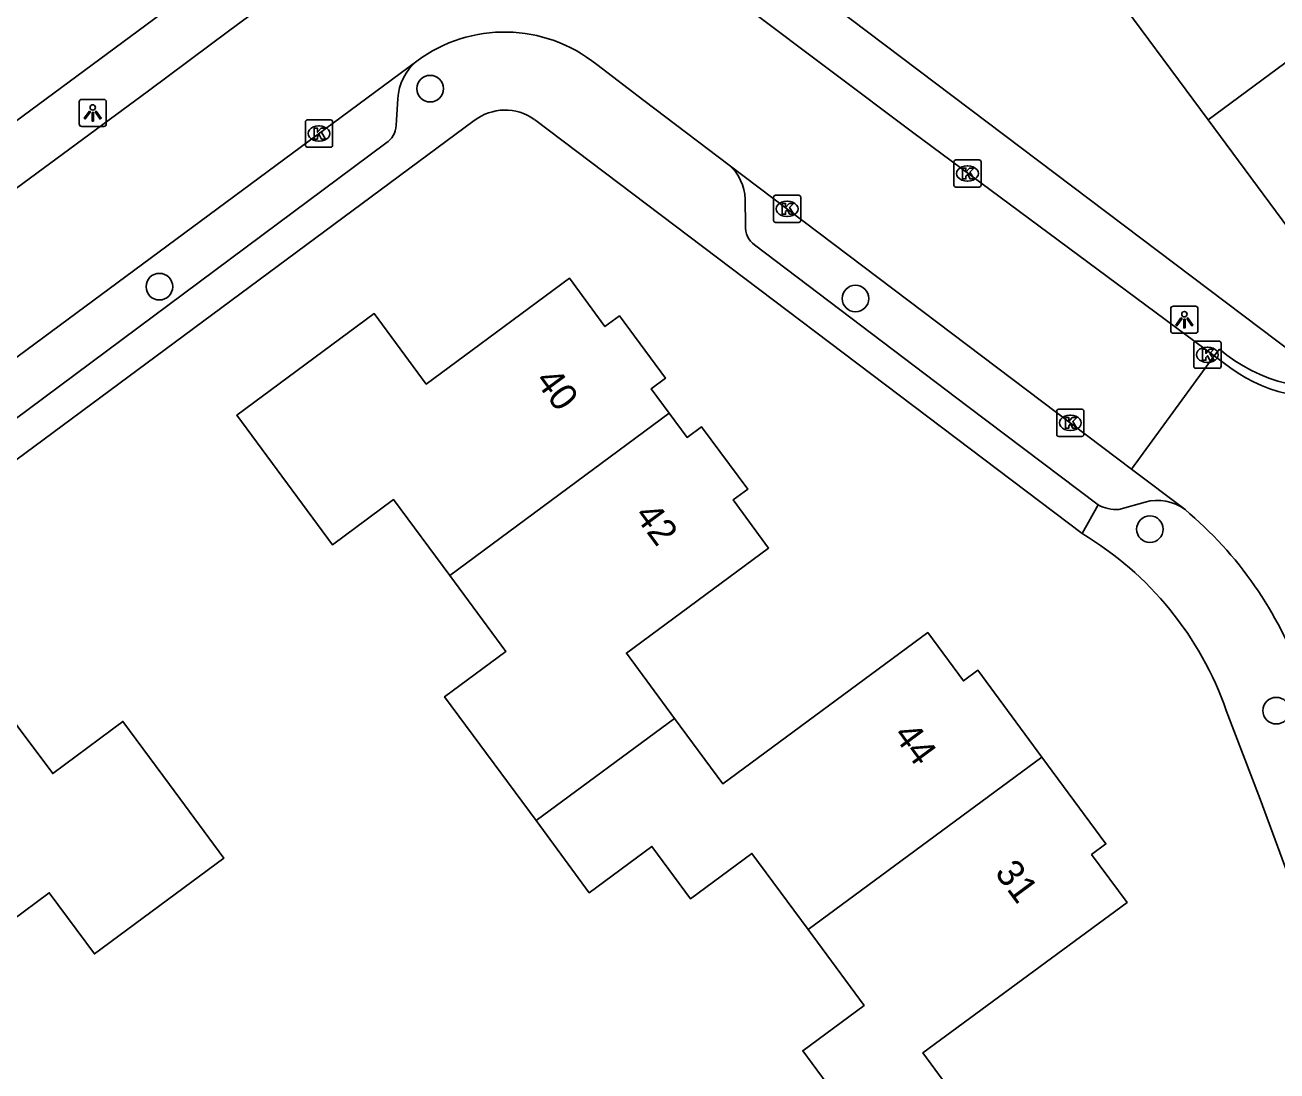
# Model space of a CAD drawing. Extents: x 163427 to 164190, y 380331 to 381641.
# Drawn here: x 163858.59 to 163904.63, y 381170.43 to 381208.88 of the extents above; entities that cross this region are included whole.
import ezdxf

# ---------------------------------------------------------------- set-up
doc = ezdxf.new("R2010")
doc.units = 0
for name, color, linetype in [('IMGEO_Boom', 7, 'Continuous'), ('IMGEO_Kolk', 7, 'Continuous'), ('IMGEO_Lichtpunt', 7, 'Continuous'), ('IMGEO_Pand', 7, 'Continuous'), ('IMGEO_Pand_nummerreeks', 7, 'Continuous'), ('IMGEO_Rijbaan_lokaal_open', 7, 'Continuous'), ('IMGEO_Voetpad_open', 7, 'Continuous')]:
    doc.layers.add(name, color=color, linetype=linetype)

msp = doc.modelspace()

# ---------------------------------------------------------------- linework, layer by layer
at = {"layer": 'IMGEO_Boom'}
for centre in [(163873.488, 381206.544), (163863.531, 381199.264), (163889.127, 381198.828), (163899.956, 381190.346), (163904.601, 381183.677)]:
    msp.add_circle(centre, 0.489, dxfattribs=at)
at = {"layer": 'IMGEO_Kolk'}
for p, q in [((163868.9, 381204.467), (163868.9, 381205.319)), ((163868.975, 381205.393), (163869.827, 381205.393)), ((163869.388, 381205.173), (163869.413, 381205.173)), ((163869.901, 381205.319), (163869.901, 381204.467)), ((163869.411, 381204.613), (163869.386, 381204.613)), ((163869.827, 381204.393), (163868.975, 381204.393)), ((163892.747, 381203), (163892.747, 381203.852)), ((163892.822, 381203.926), (163893.674, 381203.926)), ((163893.235, 381203.706), (163893.26, 381203.706)), ((163893.748, 381203.852), (163893.748, 381203)), ((163893.258, 381203.146), (163893.233, 381203.146)), ((163893.674, 381202.926), (163892.822, 381202.926)), ((163886.115, 381201.7), (163886.115, 381202.552)), ((163886.19, 381202.626), (163887.042, 381202.626)), ((163886.603, 381202.406), (163886.628, 381202.406)), ((163887.116, 381202.552), (163887.116, 381201.7)), ((163886.626, 381201.846), (163886.601, 381201.846)), ((163887.042, 381201.626), (163886.19, 381201.626)), ((163901.569, 381196.336), (163901.569, 381197.188)), ((163901.644, 381197.262), (163902.496, 381197.262)), ((163902.57, 381197.188), (163902.57, 381196.336)), ((163902.057, 381197.042), (163902.082, 381197.042)), ((163902.496, 381196.262), (163901.644, 381196.262)), ((163902.08, 381196.482), (163902.055, 381196.482)), ((163896.528, 381193.831), (163896.528, 381194.683)), ((163896.603, 381194.757), (163897.455, 381194.757)), ((163897.016, 381194.537), (163897.041, 381194.537)), ((163897.529, 381194.683), (163897.529, 381193.831)), ((163897.039, 381193.977), (163897.014, 381193.977)), ((163897.455, 381193.757), (163896.603, 381193.757))]:
    msp.add_line(p, q, dxfattribs=at)
for points in [[(163868.9, 381204.467), (163868.9, 381205.319)], [(163868.975, 381205.393), (163869.827, 381205.393)], [(163869.221, 381205.093), (163869.344, 381205.093), (163869.344, 381204.942), (163869.474, 381205.093), (163869.638, 381205.093), (163869.492, 381204.942), (163869.645, 381204.693), (163869.493, 381204.693), (163869.408, 381204.857), (163869.344, 381204.79), (163869.344, 381204.693), (163869.221, 381204.693), (163869.221, 381205.093)], [(163869.901, 381205.319), (163869.901, 381204.467)], [(163869.827, 381204.393), (163868.975, 381204.393)], [(163892.747, 381203), (163892.747, 381203.852)], [(163892.822, 381203.926), (163893.674, 381203.926)], [(163893.068, 381203.626), (163893.191, 381203.626), (163893.191, 381203.475), (163893.321, 381203.626), (163893.485, 381203.626), (163893.339, 381203.475), (163893.492, 381203.226), (163893.34, 381203.226), (163893.255, 381203.39), (163893.191, 381203.323), (163893.191, 381203.226), (163893.068, 381203.226), (163893.068, 381203.626)], [(163893.748, 381203.852), (163893.748, 381203)], [(163893.674, 381202.926), (163892.822, 381202.926)], [(163886.115, 381201.7), (163886.115, 381202.552)], [(163886.19, 381202.626), (163887.042, 381202.626)], [(163886.436, 381202.326), (163886.559, 381202.326), (163886.559, 381202.175), (163886.689, 381202.326), (163886.853, 381202.326), (163886.707, 381202.175), (163886.86, 381201.926), (163886.708, 381201.926), (163886.623, 381202.09), (163886.559, 381202.023), (163886.559, 381201.926), (163886.436, 381201.926), (163886.436, 381202.326)], [(163887.116, 381202.552), (163887.116, 381201.7)], [(163887.042, 381201.626), (163886.19, 381201.626)], [(163901.569, 381196.336), (163901.569, 381197.188)], [(163901.644, 381197.262), (163902.496, 381197.262)], [(163902.57, 381197.188), (163902.57, 381196.336)], [(163901.89, 381196.962), (163902.013, 381196.962), (163902.013, 381196.811), (163902.143, 381196.962), (163902.307, 381196.962), (163902.161, 381196.811), (163902.314, 381196.562), (163902.162, 381196.562), (163902.077, 381196.726), (163902.013, 381196.659), (163902.013, 381196.562), (163901.89, 381196.562), (163901.89, 381196.962)], [(163902.496, 381196.262), (163901.644, 381196.262)], [(163896.528, 381193.831), (163896.528, 381194.683)], [(163896.603, 381194.757), (163897.455, 381194.757)], [(163896.849, 381194.457), (163896.972, 381194.457), (163896.972, 381194.306), (163897.102, 381194.457), (163897.266, 381194.457), (163897.12, 381194.306), (163897.273, 381194.057), (163897.121, 381194.057), (163897.036, 381194.221), (163896.972, 381194.154), (163896.972, 381194.057), (163896.849, 381194.057), (163896.849, 381194.457)], [(163897.529, 381194.683), (163897.529, 381193.831)], [(163897.455, 381193.757), (163896.603, 381193.757)]]:
    msp.add_lwpolyline(points, dxfattribs=at)
for centre, start, end in [((163868.977, 381205.317), 91.552, 178.448), ((163868.977, 381205.317), 91.552, 178.448), ((163869.825, 381205.317), 1.552, 88.448), ((163869.825, 381205.317), 1.552, 88.448), ((163868.977, 381204.469), 181.552, 268.448), ((163868.977, 381204.469), 181.552, 268.448), ((163869.825, 381204.469), 271.552, 358.448), ((163869.825, 381204.469), 271.552, 358.448), ((163892.824, 381203.85), 91.552, 178.448), ((163892.824, 381203.85), 91.552, 178.448), ((163893.672, 381203.85), 1.552, 88.448), ((163893.672, 381203.85), 1.552, 88.448), ((163892.824, 381203.002), 181.552, 268.448), ((163892.824, 381203.002), 181.552, 268.448), ((163893.672, 381203.002), 271.552, 358.448), ((163893.672, 381203.002), 271.552, 358.448), ((163886.192, 381202.55), 91.552, 178.448), ((163886.192, 381202.55), 91.552, 178.448), ((163887.04, 381202.55), 1.552, 88.448), ((163887.04, 381202.55), 1.552, 88.448), ((163886.192, 381201.702), 181.552, 268.448), ((163886.192, 381201.702), 181.552, 268.448), ((163887.04, 381201.702), 271.552, 358.448), ((163887.04, 381201.702), 271.552, 358.448), ((163901.646, 381197.186), 91.552, 178.448), ((163901.646, 381197.186), 91.552, 178.448), ((163902.494, 381197.186), 1.552, 88.448), ((163902.494, 381197.186), 1.552, 88.448), ((163901.646, 381196.338), 181.552, 268.448), ((163901.646, 381196.338), 181.552, 268.448), ((163902.494, 381196.338), 271.552, 358.448), ((163902.494, 381196.338), 271.552, 358.448), ((163896.605, 381194.681), 91.552, 178.448), ((163896.605, 381194.681), 91.552, 178.448), ((163897.453, 381194.681), 1.552, 88.448), ((163897.453, 381194.681), 1.552, 88.448), ((163896.605, 381193.833), 181.552, 268.448), ((163896.605, 381193.833), 181.552, 268.448), ((163897.453, 381193.833), 271.552, 358.448), ((163897.453, 381193.833), 271.552, 358.448)]:
    msp.add_arc(centre, 0.0765, start, end, dxfattribs=at)
for centre, major_axis, ratio, start_param, end_param in [((163869.387, 381204.893), (-0.387, 0.002), 0.722429, 4.712389, 7.853982), ((163869.412, 381204.893), (-0.39, 0.002), 0.717154, 1.570796, 4.712389), ((163893.234, 381203.426), (-0.387, 0.002), 0.722429, 4.712389, 7.853982), ((163893.259, 381203.426), (-0.39, 0.002), 0.717154, 1.570796, 4.712389), ((163886.602, 381202.126), (-0.387, 0.002), 0.722429, 4.712389, 7.853982), ((163886.627, 381202.126), (-0.39, 0.002), 0.717154, 1.570796, 4.712389), ((163902.056, 381196.762), (-0.387, 0.002), 0.722429, 4.712389, 7.853982), ((163902.081, 381196.762), (-0.39, 0.002), 0.717154, 1.570796, 4.712389), ((163897.015, 381194.257), (-0.387, 0.002), 0.722429, 4.712389, 7.853982), ((163897.04, 381194.257), (-0.39, 0.002), 0.717154, 1.570796, 4.712389)]:
    msp.add_ellipse(centre, major_axis=major_axis, ratio=ratio, start_param=start_param, end_param=end_param, dxfattribs=at)
at = {"layer": 'IMGEO_Lichtpunt'}
for p, q in [((163860.581, 381206.055), (163860.581, 381205.248)), ((163860.581, 381206.055), (163860.581, 381205.248)), ((163861.483, 381206.15), (163860.675, 381206.15)), ((163861.483, 381206.15), (163860.675, 381206.15)), ((163861.577, 381205.248), (163861.577, 381206.055)), ((163861.577, 381205.248), (163861.577, 381206.055)), ((163860.675, 381205.154), (163861.483, 381205.154)), ((163860.675, 381205.154), (163861.483, 381205.154)), ((163901.626, 381198.549), (163900.818, 381198.549)), ((163901.626, 381198.549), (163900.818, 381198.549)), ((163900.724, 381198.454), (163900.724, 381197.647)), ((163900.724, 381198.454), (163900.724, 381197.647)), ((163901.72, 381197.647), (163901.72, 381198.454)), ((163901.72, 381197.647), (163901.72, 381198.454)), ((163900.818, 381197.553), (163901.626, 381197.553)), ((163900.818, 381197.553), (163901.626, 381197.553))]:
    msp.add_line(p, q, dxfattribs=at)
for points in [[(163860.955, 381205.719), (163860.994, 381205.691), (163860.806, 381205.429), (163860.768, 381205.456), (163860.955, 381205.719)], [(163861.057, 381205.671), (163861.104, 381205.671), (163861.104, 381205.349), (163861.057, 381205.349), (163861.057, 381205.671)], [(163861.167, 381205.691), (163861.205, 381205.718), (163861.392, 381205.456), (163861.353, 381205.428), (163861.167, 381205.691)], [(163901.098, 381198.118), (163901.137, 381198.09), (163900.949, 381197.828), (163900.911, 381197.855), (163901.098, 381198.118)], [(163901.31, 381198.09), (163901.348, 381198.117), (163901.535, 381197.855), (163901.496, 381197.827), (163901.31, 381198.09)], [(163901.2, 381198.07), (163901.247, 381198.07), (163901.247, 381197.748), (163901.2, 381197.748), (163901.2, 381198.07)]]:
    msp.add_lwpolyline(points, dxfattribs=at)
for centre in [(163861.08, 381205.853), (163901.223, 381198.252)]:
    msp.add_circle(centre, 0.0994, dxfattribs=at)
for centre, start, end in [((163860.675, 381206.055), 90, 180), ((163860.675, 381206.055), 90, 180), ((163861.483, 381206.055), 0, 90), ((163861.483, 381206.055), 0, 90), ((163860.675, 381205.248), 180, 270), ((163860.675, 381205.248), 180, 270), ((163861.483, 381205.248), 270, 0), ((163861.483, 381205.248), 270, 360), ((163900.818, 381198.454), 90, 180), ((163900.818, 381198.454), 90, 180), ((163901.626, 381198.454), 0, 90), ((163901.626, 381198.454), 0, 90), ((163900.818, 381197.647), 180, 270), ((163900.818, 381197.647), 180, 270), ((163901.626, 381197.647), 270, 0), ((163901.626, 381197.647), 270, 360)]:
    msp.add_arc(centre, 0.0946, start, end, dxfattribs=at)
at = {"layer": 'IMGEO_Pand'}
for points in [[(163904.482, 381219.482), (163901.694, 381217.409), (163903.749, 381214.62), (163902.33, 381213.575), (163898.262, 381210.578), (163902.096, 381205.4)], [(163902.096, 381205.4), (163909.376, 381210.792)], [(163902.096, 381205.4), (163905.935, 381200.217), (163909.984, 381203.234), (163911.394, 381204.284), (163913.566, 381201.369)], [(163882.273, 381194.614), (163881.612, 381195.505), (163882.142, 381195.898), (163880.446, 381198.187), (163879.914, 381197.798), (163878.618, 381199.573), (163875.035, 381196.931), (163873.343, 381195.683), (163871.43, 381198.277), (163866.377, 381194.536), (163869.347, 381190.515), (163869.893, 381189.776), (163872.144, 381191.439), (163874.207, 381188.646)], [(163874.207, 381188.646), (163882.273, 381194.614)], [(163882.273, 381194.614), (163882.934, 381193.722), (163883.464, 381194.115), (163885.166, 381191.818), (163884.634, 381191.429), (163885.932, 381189.655), (163880.703, 381185.796), (163882.478, 381183.391)], [(163877.381, 381179.639), (163874.02, 381184.189), (163876.271, 381185.852), (163874.207, 381188.646)], [(163850.738, 381182.979), (163851.626, 381183.634), (163851.233, 381184.167), (163853.543, 381185.871), (163853.934, 381185.345), (163855.687, 381186.647), (163858.342, 381183.072), (163859.609, 381181.366), (163862.19, 381183.282), (163863.904, 381180.962), (163865.905, 381178.254), (163861.144, 381174.732), (163859.481, 381176.98), (163856.695, 381174.92)], [(163895.984, 381181.97), (163893.632, 381185.163), (163893.099, 381184.769), (163891.786, 381186.545), (163884.252, 381180.986), (163882.478, 381183.391)], [(163882.478, 381183.391), (163877.381, 381179.639)], [(163887.383, 381175.637), (163895.984, 381181.97)], [(163895.984, 381181.97), (163898.336, 381178.777), (163897.808, 381178.385), (163899.116, 381176.624), (163891.604, 381171.094), (163893.368, 381168.698)], [(163877.381, 381179.639), (163879.341, 381176.985), (163881.641, 381178.683), (163883.06, 381176.762), (163885.319, 381178.431), (163887.383, 381175.637)], [(163888.24, 381164.922), (163886.3, 381167.548), (163888.607, 381169.253), (163887.188, 381171.174), (163889.447, 381172.843), (163887.383, 381175.637)]]:
    msp.add_lwpolyline(points, dxfattribs=at)
at = {"layer": 'IMGEO_Rijbaan_lokaal_open'}
for points in [[(163871.192, 381212.44), (163866.121, 381208.698), (163863.127, 381206.47), (163857.562, 381202.374), (163854.549, 381200.154), (163836.589, 381186.888)], [(163902.32, 381196.718), (163891.228, 381204.941), (163885.22, 381209.452), (163882.652, 381211.418), (163882.481, 381211.582)], [(163841.832, 381184.499), (163872.997, 381207.555)], [(163879.612, 381207.432), (163881.341, 381206.105), (163884.483, 381203.733)], [(163884.483, 381203.733), (163899.28, 381192.557)], [(163899.28, 381192.557), (163902.32, 381196.718)], [(163902.32, 381196.718), (163902.933, 381196.264)], [(163901.246, 381191.072), (163899.28, 381192.557)]]:
    msp.add_lwpolyline(points, dxfattribs=at)
for centre, radius, start, end in [((163876.225, 381203.225), 5.401, 51.1627, 126.7068), ((163906.314, 381200.976), 5.8, 234.3369, 285.4162), ((163892.029, 381180.095), 14.334, 19.5796, 49.9824)]:
    msp.add_arc(centre, radius, start, end, dxfattribs=at)
at = {"layer": 'IMGEO_Voetpad_open'}
for points in [[(163835.008, 381188.174), (163876.336, 381218.714)], [(163905.272, 381196.785), (163886.426, 381211.021)], [(163872.297, 381206.181), (163872.233, 381205.193)], [(163840.007, 381179.376), (163875.112, 381205.371)], [(163877.319, 381205.411), (163897.466, 381190.189)], [(163871.857, 381204.539), (163855.86, 381192.644), (163852.834, 381190.43), (163845.069, 381184.659)], [(163885.086, 381201.514), (163885.07, 381202.483)], [(163898.057, 381191.243), (163893.254, 381194.864), (163885.421, 381200.802)], [(163902.32, 381196.718), (163902.511, 381196.972)], [(163898.057, 381191.243), (163897.466, 381190.189)], [(163899.778, 381191.345), (163898.808, 381191.077)], [(163902.765, 381183.681), (163904.013, 381180.42), (163912.387, 381157.729)]]:
    msp.add_lwpolyline(points, dxfattribs=at)
for centre, radius, start, end in [((163874.249, 381206.052), 1.957, 129.7955, 176.2103), ((163876.242, 381203.905), 1.851, 54.4336, 127.643), ((163871.443, 381205.212), 0.79, 301.58, 358.6288), ((163883.334, 381202.431), 1.737, 1.73, 48.5795), ((163885.863, 381201.445), 0.78, 174.9107, 235.4837), ((163906.427, 381201.555), 6.028, 229.4886, 283.063), ((163898.704, 381192.39), 1.317, 240.5636, 274.508), ((163900.227, 381189.674), 1.73, 53.9029, 105.0275), ((163891.106, 381179.6), 12.352, 19.2943, 59.0126)]:
    msp.add_arc(centre, radius, start, end, dxfattribs=at)

# ---------------------------------------------------------------- texts
at = {"layer": 'IMGEO_Pand_nummerreeks'}
for s, rotation, p in [('40', 306.4055, (163877.318, 381195.809)), ('42', 306.4068, (163880.972, 381190.855)), ('44', 306.4756, (163890.492, 381182.778)), ('31', 306.6035, (163894.22, 381177.714))]:
    msp.add_text(s, height=1, rotation=rotation, dxfattribs=at).set_placement(p)

doc.saveas('drawing.dxf')
